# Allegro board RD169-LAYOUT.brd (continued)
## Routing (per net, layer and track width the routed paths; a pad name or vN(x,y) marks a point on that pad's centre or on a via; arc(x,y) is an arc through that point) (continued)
SIG232: length 12.4
  BOTTOM w0.5: F1.1 21.6,98.65 ; F1.1 19.4,98.65 ; F1.1 21.6,100.85 ; F1.1 19.4,100.85 ; F1.2 19.4,103.65 ; F1.2 19.4,105.85 ; F1.2 21.6,105.85 ; F1.2 21.6,103.65
SIG233: length 12.2
  BOTTOM w2: R34.1 R35.2
SIG236: length 5
  BOTTOM w0.8: R7.1 R6.2
SIG237: length 29.1
  BOTTOM w0.25: R6.1 47.6,125.58 ; R6.1 47.6,127.92 ; R6.1 48.48,126.75
  BOTTOM w0.4: C5.1 52,128.35 ; C5.1 50.65,127 ; C5.1 52,125.65
  BOTTOM w0.5: F1.4 21.6,119.15 ; F1.4 21.6,121.35 ; F1.4 19.4,121.35 ; F1.4 19.4,119.15 ; v4(53.5,127) 53.5,125.7 ; v4(53.5,127) 53.5,128.3 ; v4(53.5,127) 54.8,127 ; F1.3 19.4,116.35 ; F1.3 21.6,116.35 ; F1.3 21.6,114.15 ; F1.3 19.4,114.15 ; VAR1.1 17.26,130.11 ; VAR1.1 17.26,132.09 ; VAR1.1 19.24,132.09 ; VAR1.1 19.2,130.15
SIG239: length 5
  BOTTOM w0.4: C9.2 35.12,94.12 ; C9.2 36.88,94.12 ; C9.2 35.12,95.88 ; C9.2 36.88,95.88
SIG242: length 16.8
  BOTTOM w0.25: R7.2 36.15,127.92 ; R7.2 35.27,126.75 ; R7.2 36.15,125.58
  BOTTOM w0.4: C5.2 32,125.65 ; C5.2 33.35,127 ; C5.2 32,128.35
  BOTTOM w0.5: v4(30.5,127) 29.2,127 ; v4(30.5,127) 30.5,125.7 ; v4(30.5,127) 30.5,128.3 ; VAR1.2 26.74,126.89 ; VAR1.2 24.76,126.89 ; VAR1.2 26.74,124.91 ; VAR1.2 24.76,124.91
SIG245: length 8.1
  BOTTOM w0.3: R3.1 15.15,7 14.75,7.4 R2.2
SIG246: length 6.8
  BOTTOM w0.3: 44.35,3 40.65,3 40.4,2.75 R17.2 ; 44.35,3 R22.1 ; 44.35,3 C8.1
SIG247: length 2.8
  BOTTOM w0.3: R3.2 R4.1
SIG248: length 23.9
  TOP w0.3: v1(46.5,15.3) 47.5,14.3 47.5,8.9 45.27,6.67 v1(41,6.67)
  BOTTOM w0.3: D11.C 49.1,16.2 48.7,15.8 48.7,14.6 48.4,14.3 D12.C 46.7,14.3 46.5,14.5 v1(46.5,15.3) ; U1.7 v1(41,6.67)
SIG250: length 6.2
  BOTTOM w0.3: D7.A 47.2,9.4 46.6,10 R27.1
SIG255: length 2.7
  BOTTOM w0.4: R47.2 136.97,29.9 137.82,29.05 D17.C
SIG256: length 3.3
  BOTTOM w0.3: R9.2 51,10.5 49.55,11.95 D4.C
SIG267: length 137.3
  BOTTOM w0.4: U6.1 U6.2 142.26,35.63 139.75,33.12 139.75,29.35 140.22,28.88 141.75,28.88 146,24.62 146,5.5 142.62,2.12 106.88,2.12 100.1,8.9 95,8.9 92,5.9 92,3.12 90.25,1.38 54.92,1.38 D24.A
SIG270: length 1.3
  BOTTOM w0.4: U6.7 U6.6
SIG278: length 19.2
  TOP w0.8: v1(74.1,111.25) 72.5,111.25 69.36,114.39 v1(69.36,116.25)
  BOTTOM w0.8: U2.6 v1(69.36,116.25) 67.88,116.25 67.78,116.15 C10.1 ; v1(74.1,111.25) R26.2 74.1,108.38 73.72,108 C11.2
SIG280: length 3.9
  BOTTOM w0.8: 77.83,111.5 76.4,111.5 75.9,111 R26.1
SIG281: length 8
  BOTTOM w0.6: R14.1 68,123.85 67.95,123.9 C4.2
  BOTTOM w0.8: C4.2 65,122.88 65.1,122.78 R11.2
SIG283: length 2.9
  BOTTOM w0.8: R11.1 61.9,122.78 62,122.88 R10.2
SIG284: length 8.2
  BOTTOM w0.8: T1.3 74.38,122 74.05,122.33 72.25,122.33 72.25,120.47 71.91,120.12 U2.8
SIG285: length 2
  BOTTOM w0.8: R33.1 C18.2
SIG286: length 19.8
  TOP w0.8: T1.5 74.28,115.6 69,120.88 v1(69,122.4)
  BOTTOM w0.8: T1.5 79.15,115.6 81.17,113.58 81.17,111.5 ; R23.1 v1(69,122.4)
SIG287: length 7.7
  BOTTOM w0.8: 93.33,126.5 92,126.5 90.65,125.15 C18.1 88.05,125.15 88,125.2 T1.9
SIG288: length 10.2
  BOTTOM w0.8: R21.1 R18.1 63.4,118.75 64.03,119.38 68,119.38 ; R23.2 68,119.38 ; 68,119.38 68.09,119.28 U2.5
SIG290: length 5.7
  BOTTOM w0.8: U2.4 68.09,110.88 67.72,110.5 R8.1 R13.1
SIG316: length 2.1
  BOTTOM w0.8: 73.5,97.11 R67.1 73.5,99.25
SIG318: length 2.2
  BOTTOM w0.8: 73.5,92.75 R65.2 R66.1
SIG319: length 3
  BOTTOM w0.4: 78.5,45 R37.2 81.5,45
SIG320: length 3
  BOTTOM w0.4: 73.5,45 R36.2 R37.1 76.5,45
SIG321: length 2.2
  BOTTOM w0.8: 73.5,88.5 R64.2 R65.1 73.5,90.7
SIG322: length 7
  BOTTOM w0.3: 70,21 R40.1 R39.2 70,28
SIG323: length 2.2
  BOTTOM w0.8: 73.5,84.25 R63.2 R64.1 73.5,86.5
SIG328: length 54.4
  TOP w0.4: v1(72.25,30) v1(72.25,42)
  BOTTOM w0.3: 70,30 v1(72.25,30)
  BOTTOM w0.4: 81.5,43 80.5,42 v1(72.25,42) 67.62,42 65.5,44.12 65.5,51 66.75,52.25 C24.2
SIG332: length 2.3
  BOTTOM w0.5: R54.2 R55.1
SIG333: length 4
  BOTTOM w0.5: R53.2 R54.1
SIG334: length 2.3
  BOTTOM w0.5: R52.2 R53.1
SIG335: length 4
  BOTTOM w0.5: R55.2 R56.1
SIG341: length 15.8
  BOTTOM w0.4: R50.2 Q2.C Q5.C 60.5,98.85 62.85,101.2 R51.2
SIG345: length 15.4
  BOTTOM w0.4: U3.8 84.25,3.5 84.75,3 89.8,3 90.5,3.7 90.5,6.75 92,8.25 R42.2
SIG348: length 8.8
  BOTTOM w0.4: C29.1 70.6,99.65 69.2,101.05 D19.C 67.08,101.05 66.12,102 R51.1
SIG351: length 2.6
  BOTTOM w0.4: R20.1 77.16,9.75 77.25,9.65 U3.4
SIG353: length 7.2
  BOTTOM w0.4: Q2.B 63.55,95 64.05,94.5 65.88,94.5 66.38,94 66.38,92.25 66.88,91.75 R30.1
SIG354: length 4.9
  BOTTOM w0.3: C7.1 80.65,6.57 80.1,7.12 U3.2
SIG356: length 5.7
  BOTTOM w0.3: U3.5 83.1,9.65 82.65,10.11 R29.1 C16.1
SIG357: length 4.9
  BOTTOM w0.3: R31.1 57.5,2.55 57.75,2.3 Q3.B
SIG358: length 2.6
  BOTTOM w0.3: C14.1 79.4,12.5 80.15,11.75 R29.2
SIG359: length 19.6
  BOTTOM w0.3: U3.3 80,8.38 80.12,8.51 80.12,10.75 79.88,11 77.5,11 77,11.5 R19.2
  BOTTOM w0.4: 76.15,6.75 73,6.75 72.7,6.45 D5.C ; 76.15,6.75 C6.1 77,7.75 77.64,8.38 U3.3 ; 76.15,6.75 R15.1
SIG381: length 14
  BOTTOM w0.4: R78.2 90.38,75.4 90.45,75.33 92.88,75.33 92.95,75.25 R82.1 94.35,74.61 Q8.G
SIG383: length 13.6
  TOP w0.4: Q7.G 79.96,71.5 80,71.54 v1(80,77.12)
  BOTTOM w0.4: R81.1 v1(80,77.12) 80,78.33 78.58,78.33 78.5,78.4 R77.2
SIG387: length 5.6
  BOTTOM w0.4: R74.1 R77.1 78.5,81.6 78.58,81.67 80,81.67
SIG392: length 4.8
  BOTTOM w0.4: R76.1 R78.1 90.38,78.6 90.45,78.67 91.75,78.67
SIG395: length 9.3
  BOTTOM w0.4: C46.2 97.38,92.5 98.4,93.53 R86.1 98.4,95.4 99.4,96.4 R73.2 R85.1
SIG396: length 15.7
  TOP w0.4: v1(94.75,96.12) 95.25,95.62 95.25,92.25 v2(98,89.5)
  BOTTOM w0.4: C51.1 93.85,97.03 v1(94.75,96.12) ; C51.1 93,98.25 92.9,98.35 R117.2 ; C51.1 C52.1 ; v2(98,89.5) C44.2
SIG401: length 10
  BOTTOM w0.4: 90,102.35 R59.1 R72.2 R71.2 ; 90,102.35 88.94,102.35 88.69,102.1 U5.8 ; 90,102.35 C28.1
SIG404: length 1.9
  BOTTOM w0.4: R70.2 C30.1
SIG406: length 6.2
  BOTTOM w0.4: U5.7 87.42,99.75 87.67,99.5 89.5,99.5 90.15,100.15 R117.1
SIG407: length 18.2
  TOP w0.4: v1(80,85.75) 80,91.66 v1(82.34,94)
  BOTTOM w0.4: C38.2 82,96.9 82.34,96.56 U5.14 v1(82.34,94) ; 80,84.08 D22.C v1(80,85.75)
SIG409: length 2.2
  BOTTOM w0.4: 94.17,86.5 R97.2
SIG415: length 2.5
  BOTTOM w0.4: R88.2 156.5,109.15 156.65,109 C50.2
SIG416: length 2.4
  BOTTOM w0.4: C55.1 178.05,121.85 177.95,121.75 U9.3
SIG417: length 4.7
  BOTTOM w0.4: R89.1 158.6,101.85 159.1,101.35 C49.1
SIG418: length 2.4
  BOTTOM w0.4: U8.3 177.95,105.25 178.05,105.35 C53.1
SIG420: length 8
  BOTTOM w0.4: R98.2 182,101.6 181.5,102.1 C54.1 179.7,102.1 179,101.4 U8.4
SIG422: length 2.6
  BOTTOM w0.4: R94.1 Q13.4
SIG423: length 2.6
  BOTTOM w0.4: R95.1 Q11.4
SIG425: length 27.4
  TOP w0.4: v1(158.5,113.6) v1(171.5,113.6) v1(171.5,118.35)
  BOTTOM w0.4: R92.2 v1(171.5,113.6) ; v1(158.5,113.6) R93.2 ; U9.1 176.05,119.9 174.5,118.35 R96.2 v1(171.5,118.35)
SIG426: length 2.6
  BOTTOM w0.4: R92.1 Q12.4
SIG430: length 2.8
  BOTTOM w0.4: R93.1 Q10.4
SIG431: length 27.8
  TOP w0.4: v1(158.62,97.1) v1(171.5,97.1) v1(171.5,102.35)
  BOTTOM w0.4: v1(158.62,97.1) R95.2 ; v1(171.5,102.35) R91.2 175.15,102.35 176.05,103.25 U8.1 ; R94.2 v1(171.5,97.1)
SIG435: length 6.8
  BOTTOM w0.4: U9.4 179.03,117.9 179.47,118.35 C58.1 181.28,118.35 182,117.62 R99.1
SIG438: length 2.7
  BOTTOM w0.4: R110.1 158.6,35.5 158.5,35.4 R109.2
SIG439: length 3
  BOTTOM w0.4: R110.2 162.85,34 162.9,33.95 R111.1
SIG440: length 2.3
  BOTTOM w0.4: R116.1 168.09,13.24 Q16.4
SIG441: length 33.6
  BOTTOM w0.3: C80.1 169.1,25.1 ; C80.1 168.25,24.25 ; C80.1 169.1,23.4 ; C80.1 169.95,24.25 ; C78.2 168.75,29.4 C81.1
  BOTTOM w0.4: C65.1 157.78,15.4 157.83,15.35 U11.1 160.97,15.35 162.25,16.62 162.25,17.89 ; U11.6 163.15,17.89
  BOTTOM w1: TB2.4 181.37,29.63 ; TB2.4 181.37,26.37 ; TB2.4 184.63,26.37 ; TB2.4 184.63,29.63 ; TB2.3 184.63,37.37 ; TB2.3 181.37,40.63 ; TB2.3 181.37,37.37 ; TB2.3 184.63,40.63
SIG442: length 2.8
  BOTTOM w0.3: C73.2 164.4,13.2 164.5,13.3 U11.8
SIG444: length 2.3
  BOTTOM w0.4: Q15.4 174.59,13.24 R115.1
SIG445: length 2.3
  BOTTOM w0.4: R113.1 181.09,13.24 Q14.4
SIG446: length 2.8
  BOTTOM w0.4: R104.1 157.28,17.35 158.01,16.61 U11.2
SIG447: length 3
  BOTTOM w0.4: R112.1 166.15,34 166.1,33.95 R111.2
SIG452: length 11
  BOTTOM w0.3: R101.1 146.78,56.6 148.03,55.35 148.75,55.35 ; R100.2 149.25,55.35 ; 149.25,55.35 148.75,55.35 ; 149.25,55.35 149,55.1 ; 149,55.1 148.75,55.35 ; 149,55.1 ZD3.C 149,53.58
SIG454: length 3.1
  BOTTOM w0.3: R105.1 141.15,58.85 141.5,59.2 141.5,59.9 141.85,60.25 C64.1
SIG455: length 7.8
  BOTTOM w0.3: C68.1 R107.1 146.15,62.35 147.62,60.88 147.62,59.67 148.05,59.25 R106.2
SIG458: length 13.5
  BOTTOM w0.3: 148.95,65.5 D25.A 148.95,68.42 148.4,68.97 C70.2 ; 148.95,65.5 151.5,65.5 151.75,65.25 R114.1 ; 148.95,65.5 147.88,65.5 147.55,65.17 D26.C
SIG460: length 11.6
  TOP w0.3: v2(145.4,61.12) v2(145.4,67.75)
  BOTTOM w0.3: 145.4,60.4 145.25,60.25 C64.2 ; 145.4,60.4 v2(145.4,61.12) ; 145.4,60.4 R103.2 ; U10.1 145,66.35 145.4,66.75 v2(145.4,67.75)
SIG461: length 11.3
  BOTTOM w0.3: R25.1 R24.2 46.62,6 46,6.62 46,8.55 45.75,8.8 44.12,8.8 43.3,7.97 U1.5
SIG462: length 4.1
  BOTTOM w0.3: U1.1 38.8,5.2 38.6,5 R16.2 R17.1
SIG464: length 7.2
  BOTTOM w0.4: U5.9 88.69,94.43 89.03,94.1 C34.1 ; C34.1 R80.1 ; C34.1 R79.2
SIG466: length 18.6
  TOP w0.4: v1(90.25,98.62) 96.12,98.62 v1(96.75,99.25)
  BOTTOM w0.4: R73.1 97.6,98.9 97.25,99.25 v1(96.75,99.25) ; v1(90.25,98.62) 87.25,98.62 86.16,99.72 U5.6 86.16,102.5 86.41,102.75 87.75,102.75 88,103 C27.1
SIG469: length 4
  BOTTOM w0.3: R62.1 R60.2 R61.1
SIG470: length 9.8
  BOTTOM w0.3: 24.75,2.62 24.75,3.85 23.85,4.75 R48.2 23.85,6.25 24.75,7.15 24.75,9.88 24.45,10.18 U4.2
SIG471: length 4.8
  BOTTOM w0.3: R69.1 20.4,10.5 ; 20.4,10.5 R62.2 ; 20.4,10.5 21.75,10.5 22.07,10.82 U4.3
SIG489: length 6.2
  BOTTOM w0.3: U1.6 43.5,7.33 43.75,7.08 43.75,6.3 44,6.05 D7.C 45.65,6.05 46.15,5.55 R22.2
SIG490: length 3.4
  BOTTOM w0.3: D3.C 69.8,7.47 69.05,6.72 D5.A
SIG491: length 13.8
  BOTTOM w0.3: U10.2 142.55,65.15 142.75,64.95 C68.2 ; R105.2 R108.1 141.48,62.85 141.75,63.12 141.75,63.77 142.12,64.15 C68.2 ; D25.C 146.55,64.7 146,64.15 R107.2 C68.2
SIG508: length 72.6
  TOP w0.4: v1(121.75,64.02) 121.75,65 114.75,72 114.75,82.88 113.12,84.5 97.88,84.5 93.53,88.85 v1(93.5,88.85) 93.5,90.88 88.5,95.88 86,95.88 84.89,96.99 v1(84.89,98.88)
  BOTTOM w0.4: PC1.C v1(121.75,64.02) ; v1(93.5,88.85) R70.1 94.75,88 95,87.75 97.78,87.75 98.15,87.38 R97.1 ; U5.5 v1(84.89,98.88)
SIG519: length 7.5
  BOTTOM w0.3: R32.1 20,22.18 19.75,22.43 17,22.43 17,25.99 17.02,26.02
SIG520: length 2.4
  BOTTOM w0.3: 13.25,22.68 R12.2
SIG521: length 2.3
  BOTTOM w0.8: 72.25,125.67 70.9,125.67 70.88,125.65 R14.2
SIG522: length 2.2
  BOTTOM w0.4: 80,87.42 R83.1
SIG529: length 44.5
  BOTTOM w0.4: 86.25,15.93 86.33,15.85 R46.2 91.9,15.85 96.63,11.12 100.88,11.12 107.62,4.38 117.88,4.38 118.9,5.4 R49.2 118.9,9.72 118.2,10.43 Q6.1
SIG535: length 23.3
  TOP w2: R34.2 29.85,22.65 RL1.4
  BOTTOM w0.5: D10.4 51.13,49.62 ; D10.4 48.87,49.62 ; D10.4 48.87,51.88 ; D10.4 51.13,51.88
SIG536: length 23.6
  TOP w0.4: C23.1 24.8,39.45 ; C23.1 26.7,37.55 ; C23.1 26.7,39.45 ; C23.1 24.8,37.55
  TOP w0.5: D10.1 26.13,49.62 ; D10.1 23.87,49.62 ; D10.1 23.87,51.88 ; D10.1 26.13,51.88
  BOTTOM w0.4: C23.1 26.7,39.45 ; C23.1 24.8,37.55 ; C23.1 24.8,39.45 ; C23.1 26.7,37.55
  BOTTOM w0.5: D10.1 26.13,51.88 ; D10.1 23.87,51.88 ; D10.1 23.87,49.62 ; D10.1 26.13,49.62
U8_5: length 5.7
  BOTTOM w0.3: C49.2 160.05,99.25 ; C49.2 160.9,98.4 ; C49.2 161.75,99.25 ; C49.2 160.9,100.1
  BOTTOM w0.4: 176.09,99.1 176.05,99.14 U8.5
  vias: v3(138.5,99) v3(138.5,97) v3(138.5,95) v3(138.5,93) v3(138.5,91) v3(140.5,100) v3(140.5,98) v3(140.5,96) v3(140.5,94) v3(140.5,92) v3(140.5,90) v3(142.72,90) v3(142.75,96) v3(145.01,100) v3(145,98) v3(145,96) v3(145,94) v3(145,92) v3(145,90)
U9_5: length 4.1
  BOTTOM w0.3: R88.1 156.5,114.55 ; R88.1 156.5,112.65 ; R88.1 155.25,113.6 ; U9.5 176.05,116.95
  vias: v3(138.5,131.5) v3(138.5,129.5) v3(138.5,127.5) v3(138.5,125.5) v3(138.5,123.5) v3(138.5,121.5) v3(140.5,132.5) v3(140.5,130.5) v3(140.5,128.5) v3(140.5,126.5) v3(140.5,124.5) v3(140.5,122.5) v3(140.5,120.5) v3(142.75,132.5) v3(142.75,130.5) v3(142.75,124.5) v3(145,132.5) v3(145,130.5) v3(145,128.5) v3(145,126.5) v3(145,124.5) v3(145,122.5) v3(145,120.5) v3(147,131.53) v3(147,129.53) v3(147,127.53) v3(147,125.38) v3(147,123.38)
VREF: length 15.5
  BOTTOM w0.3: R84.2 C43.1 31.95,11.4 32.75,10.6 U7.2 U7.1 35.9,10.6 36.15,10.35 C3.1 39.62,8.75 39.88,8.5 39.88,6.92 39.62,6.67 U1.2
VSENSE: length 52.2
  BOTTOM w0.3: 70,19 R40.2 70,17 63,10 Q4.C ; Q4.C 63,3.5 62.75,3.25 Q3.C ; Q4.C 69.12,4.25 70.47,2.9 82,2.9 82.6,3.5 82.6,8.13 82.85,8.38 U3.6 85.64,8.38 85.75,8.5 R41.1
  BOTTOM w0.4: C21.1 R41.1

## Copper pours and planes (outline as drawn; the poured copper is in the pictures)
12VREC on TOP: outline of 183 points within 137.5,9.5 191,134 ; 30 cut-outs
12VREC on BOTTOM: outline of 139 points within 161,9 191,16.88 ; 2 cut-outs
12VREC on BOTTOM: 138,102 137.5,102.5 137.5,118.2 138.05,118.75 145.45,118.75 146,118.2 146,102.5 145.5,102
GND_PRI_P on TOP: 62,114.94 62.01,115 62.04,115.04 62.46,115.46 62.5,115.49 62.56,115.5 62.97,115.5 63.12,115.38 63.03,115.21 62.58,114.92 62.29,114.47 62.12,114.38 62,114.53
GND_PRI_P on TOP: 135.72,71 118,71 116,73 116,86.5 116.5,87 119.5,87 120,86.5 120,76.5 121,75.5 134.49,75.5 137,78.01 137,82.18 137.82,83 140,83 140.5,82.5 140.5,75.78 ; 3 cut-outs
GND_PRI_P on TOP: outline of 192 points within 62,101.75 107,130.5 ; 5 cut-outs
GND_PRI_P on TOP: outline of 615 points within 62,82 101.5,113 ; 2 cut-outs
GND_PRI_P on TOP: outline of 153 points within 65,8.1 121,87
GND_PRI_P on BOTTOM: 135,50.38 99.12,50.38 98.5,51 98.5,60.5 99,61 102.36,61 105,63.64 105,66.8 104.3,67.5 104.3,70 108,73.7 108,85.17 110.21,87.38 110.28,87.45 114.5,91.67 114.5,119.12 114,119.62 103.38,119.62 101,117.25 101,111.8 100.45,111.25 98.75,111.25 98.75,111.94 99.97,113.16 100,113.18 100.04,113.22 100.06,113.25 100.08,113.27 100.09,113.3 100.11,113.32 100.14,113.38 100.16,113.43 100.18,113.49 100.19,113.55 100.2,113.61 100.2,113.67 100.2,113.71 100.2,124.1 100.35,124.25 118.05,124.25 120,122.3 120,79 120.37,78.63 120.83,78.17 121,78 136.8,78 136.97,78.17 137.3,78.5 137.3,82.5 137.8,83 139.8,83 140.3,82.5 140.3,75.79 136.01,71.5 135.14,71.5 134.14,70.5 131.76,70.5 127.76,66.5 120.38,66.5 119.38,65.5 119.38,60.13 119.74,59.75 120.38,59.12 127.76,59.12 131.89,55 135,55 135.5,54.5 135.5,50.87 ; 6 cut-outs
GND_PRI_P on BOTTOM: outline of 738 points within 60.95,82.5 101,110.75 ; 19 cut-outs
GND_PRI_P on BOTTOM: outline of 98 points within 77.35,100.2 81.75,103.99
GND_PRI_P on BOTTOM: 115.7,7.5 108.5,7.5 101.62,14.38 97.62,14.38 93.12,18.88 87.21,18.88 83.58,22.5 78.5,22.5 78,23 78,26 78.5,26.5 91.91,26.5 93,27.59 93,33 93.5,33.5 112.5,33.5 113,33 113,30.25 112.5,29.75 105.88,29.75 104.5,28.37 104.5,14.88 105.88,13.5 115.95,13.5 116.2,13.25 116.2,8 ; 3 cut-outs
GND_PRI_P on BOTTOM: outline of 150 points within 60.5,103 92.25,119.7 ; 8 cut-outs
GND_PRI_P on BOTTOM: 95.4,113.3 95.4,111.38 95.22,111.51 94.27,112.47 94.25,112.5 94.2,112.54 94.18,112.56 94.15,112.58 94.13,112.59 94.1,112.61 94.05,112.64 93.99,112.66 93.93,112.68 93.87,112.69 93.81,112.7 93.75,112.7 93.72,112.7 93.35,112.7 93.31,112.74 93.24,112.81 93.17,112.87 93.09,112.93 93.01,112.98 92.92,113.02 92.83,113.05 92.74,113.08 92.64,113.09 92.55,113.1 92.45,113.1 92.36,113.09 92.26,113.08 92.17,113.05 92.08,113.02 91.99,112.98 91.91,112.93 91.83,112.87 91.76,112.81 91.69,112.74 91.63,112.67 91.57,112.59 91.52,112.5 89.08,112.5 90.46,113.88 92.17,113.88 92.49,114.04 93.09,114.63 93.24,114.91 93.25,115.02 93.25,119.7 95.8,119.7 98.8,122.7 98.8,113.96 97.96,113.12 97.1,113.12 97.1,113.3 ; 1 cut-out
GND_PRI_P on BOTTOM: 69,53.5 68.5,54 68.5,67.62 65,71.12 65,77.48 65.5,77.97 68.5,77.97 69,77.48 69,71.88 72.5,68.38 72.5,54 72,53.5
GND_PRI_S on TOP: outline of 1022 points within 14.5,1 155,44.5 ; 4 cut-outs
GND_PRI_S on BOTTOM: outline of 132 points within 57.95,2 69.86,9.75
GND_PRI_S on BOTTOM: outline of 130 points within 83.1,3.5 90.33,14.62 ; 4 cut-outs
GND_PRI_S on BOTTOM: outline of 255 points within 36.6,1 57.26,6.59
GND_PRI_S on BOTTOM: outline of 107 points within 134.25,26.75 144.4,38.25
GND_PRI_S on BOTTOM: outline of 542 points within 15.88,1.7 43.84,20.25 ; 7 cut-outs
GND_PRI_S on BOTTOM: outline of 367 points within 63.45,3.35 117.4,22 ; 6 cut-outs
GND_PRI_S on BOTTOM: 142.12,29.21 141.88,29.36 141.82,29.39 141.8,29.46 141.8,30.6 141.55,30.6 141.48,30.63 141.45,30.7 141.45,32.95 141.46,32.99 141.48,33.02 142.29,33.84 142.33,33.86 142.36,33.87 142.4,33.87 142.47,33.84 142.5,33.77 142.5,32.49 144.2,32.49 144.2,33.77 144.23,33.84 144.3,33.87 144.43,33.87 144.51,33.85 144.55,33.77 144.55,33.7 145.95,33.7 145.95,33.8 145.98,33.87 146.05,33.9 146.45,33.9 146.52,33.87 146.55,33.8 146.55,33.7 147.95,33.7 147.95,35.1 146.55,35.1 146.55,35 146.52,34.93 146.45,34.9 146.05,34.9 145.98,34.93 145.95,35 145.95,35.1 145.9,35.1 145.83,35.13 145.8,35.2 145.8,35.9 145.83,35.97 145.9,36 147.83,36 147.87,35.99 147.9,35.97 148.35,35.53 148.37,35.5 148.38,35.46 148.38,31.92 148.37,31.88 148.35,31.85 146.1,29.6 146.1,25.7 146.07,25.63 146,25.6 145.77,25.6 145.74,25.61 145.7,25.63 ; 2 cut-outs
GND_SEC on TOP: 136.5,64.44 136.51,64.5 136.54,64.54 137.46,65.46 137.5,65.49 137.56,65.5 138.63,65.5 143.83,70.71 143.88,70.74 143.94,70.75 146.94,70.75 147,70.74 147.04,70.71 147.46,70.29 147.49,70.25 147.5,70.19 147.5,63.58 147.77,63.31 151.18,59.9 151.46,59.63 151.49,59.58 151.5,59.52 151.5,56.69 151.49,56.63 151.46,56.58 151.04,56.17 151,56.14 150.94,56.12 145.95,56.12 145.89,56.14 145.83,56.19 145.08,57.21 144.19,58.23 143.21,59.16 142.47,59.75 142.15,60.01 141.03,60.76 140.25,61.18 139.84,61.41 138.6,61.95 137.32,62.39 136.74,62.54 136.7,62.56 136.67,62.58 136.54,62.71 136.51,62.75 136.5,62.81 ; 1 cut-out
GND_SEC on BOTTOM: outline of 808 points within 140.95,1 191,126 ; 49 cut-outs
GND_SEC on BOTTOM: outline of 159 points within 137.38,62.34 148.5,70.75 ; 1 cut-out
+HV on TOP: 127,17 126,18 126,27 127,28 145,28 146,27 146,18 145,17
+HV on BOTTOM: 141.5,17.25 126.5,17.25 126,17.75 126,38.83 124.33,40.5 87.5,40.5 86,42 86,50.8 85.57,51.23 82.2,54.6 80.1,54.6 78.23,56.47 77.5,57.2 77.5,62.25 81.65,66.4 81.65,69.45 81.9,69.7 83.1,69.7 83.35,69.45 83.35,66.4 84.15,65.6 84.15,61.65 84.8,61 95.5,61 96.5,60 96.5,50.17 98.3,48.38 136,48.38 136.5,47.88 136.5,41.75 133.93,39.18 132,37.25 132,26.88 134.38,24.5 141.5,24.5 142,24 142,17.75 ; 3 cut-outs
FG1 on BOTTOM: 190,1 177.5,1 177,1.5 177,7.5 177.5,8 190.5,8 191,7.5 191,2 ; 1 cut-out
FG2 on BOTTOM: 3.6,77.5 1,80.1 1,133 2,134 8,134 9,133 9,126.75 8,125.75 5.25,125.75 4,124.5 4,83 5.25,81.75 13,81.75 14,80.75 14,78.5 13,77.5
FG3 on BOTTOM: 8,1 1.5,1 1,1.5 1,45.5 1.5,46 5.25,46 6,45.25 6,30.5 4.25,28.75 4.25,10.25 8.5,6 8.5,1.5 ; 2 cut-outs
HS on BOTTOM: 101.66,63.12 97.59,63.12 93.42,67.3 84.45,67.3 84.19,67.56 84.19,69.45 84.44,69.7 94.55,69.7 98.63,65.62 100.62,65.62 101.65,66.65 101.65,73.71 101.79,73.85 102.5,74.56 102.5,87 103.38,87.88 105.3,89.8 108.25,92.75 108.25,104.5 108.24,104.81 108.2,105.11 108.13,105.41 108.04,105.7 107.92,105.98 107.8,106.21 107.78,106.25 107.62,106.51 107.43,106.75 107.23,106.98 107,107.18 106.76,107.37 106.5,107.53 106.23,107.67 105.95,107.79 105.66,107.88 105.35,107.95 105.06,107.99 104.75,108 103.5,108 103,108.5 103,112 103.5,112.5 112,112.5 112.5,112 112.5,92.5 108.96,88.96 107.74,87.74 106,86 106,74.53 105.44,73.97 103.35,71.88 103.35,64.81 ; 1 cut-out
ISENSE on BOTTOM: 30.7,14.3 29.2,14.3 28.6,14.9 28.6,18.3 29.8,19.5 32.8,19.5 36.1,22.8 36.1,28.85 47.25,40 80.25,40 80.75,39.5 80.75,34.67 82.42,33 91.5,33 92,32.5 92,28 91.5,27.5 78.5,27.5 78,28 78,30.75 77.5,31.25 73.75,31.25 69.9,35.1 48.5,35.1 44.57,31.17 43.67,30.27 42.5,29.1 42.5,23.2 40,20.7 36.82,17.52 36.67,17.37 36.5,17.2 33.6,17.2 ; 4 cut-outs
ISNS_VCR on TOP: 134.75,83.5 124.25,83.5 123.75,84 123.75,89.45 117.1,96.1 103.4,96.1 102.8,96.7 102.8,100.6 103.4,101.2 121.5,101.2 123,99.7 123,98.5 124.5,97 124.8,97 135.25,86.55 135.25,84 ; 3 cut-outs
SIG219 on BOTTOM: 44.8,86.6 41.7,86.6 41.1,87.2 41.1,89.1 41.6,89.6 42.3,89.6 46.5,93.8 46.5,103.5 47.2,104.2 51.5,104.2 52.5,103.2 52.5,94.3 ; 1 cut-out
SIG222 on BOTTOM: 38.54,73.84 39.96,75.26 40,75.29 40.06,75.3 55.14,75.3 55.24,75.26 56.56,73.94 56.59,73.9 56.6,73.84 56.6,69.76 56.56,69.66 55.32,68.42 54.84,67.94 54.8,67.91 54.74,67.9 46,67.9 44.5,66.4 44.5,48.81 44.46,48.71 44.04,48.29 44,48.26 43.94,48.25 41.06,48.25 40.96,48.29 40.54,48.71 40.51,48.75 40.5,48.81 40.5,69.1 38.54,71.06 38.51,71.1 38.5,71.16 38.5,73.74 ; 2 cut-outs
SIG226 on BOTTOM: 12.5,55.44 12.51,55.5 22.6,65.6 22.6,77.34 22.61,77.4 27.96,82.76 27.99,82.78 28.03,82.8 28.06,82.8 51.6,82.8 52.8,84 52.8,88.44 52.81,88.5 53.46,89.16 53.49,89.18 53.53,89.2 53.56,89.2 56.04,89.2 56.1,89.19 56.89,88.4 56.9,88.34 56.9,79.96 56.89,79.9 55.34,78.34 55.31,78.32 55.27,78.3 55.24,78.3 31.7,78.3 30.37,76.97 29.25,75.85 28.6,75.2 28.6,65.5 30.9,63.2 34.46,63.2 34.55,63.17 34.6,63.1 36.99,60.7 37,60.64 37,48.81 36.99,48.75 36.54,48.29 36.51,48.27 36.47,48.25 36.44,48.25 33.31,48.25 33.25,48.26 33.21,48.29 32.79,48.71 32.76,48.75 32.75,48.81 32.75,55.75 30.4,58.1 18.4,58.1 16,55.7 16,41.31 15.99,41.25 15.54,40.79 15.51,40.77 15.47,40.75 15.44,40.75 13.06,40.75 13,40.76 12.96,40.79 12.54,41.21 12.51,41.25 12.5,41.31 ; 3 cut-outs
SIG231 on TOP: 121.5,8 121,8.5 121,13.12 119.12,15 106.5,15 106,15.5 106,27.75 106.5,28.25 123.6,28.25 124.5,27.35 124.5,17.38 126.07,15.81 126.19,15.69 126.38,15.5 145,15.5 146,14.5 146,8.5 145.5,8
SIG231 on BOTTOM: 122,5 121,6 121,13.12 119.12,15 106.5,15 106,15.5 106,27.75 106.5,28.25 113.12,28.25 114.5,29.63 114.5,33.62 113.12,35 83.25,35 83.21,35.04 82.75,35.5 82.75,39 83.25,39.5 85.67,39.5 86.67,38.5 123.5,38.5 124,38 124,16.94 125.69,15.25 134.1,15.25 134.1,13.45 137.9,13.45 137.9,15.25 142,15.25 142.5,14.75 142.5,6 141.5,5
SIG237 on BOTTOM: 22.5,113.5 17.8,113.5 16,115.3 16,133 17,134 53.5,134 55.12,132.38 55.12,124.62 53,122.5 53,116.25 52.82,116.07 51.75,115 48.87,115 47.81,116.07 47,116.87 47,125.7 48.35,125.7 48.35,127.8 47,127.8 47,130.3 46.17,131.12 24,131.12 21.5,128.62 21.5,123 24.5,120 24.5,115.5 ; 4 cut-outs
SIG239 on BOTTOM: 30.2,86.7 24.1,86.7 23.5,87.3 23.5,89.5 24,90 26.12,90 31.5,95.38 31.5,103.2 32.8,104.5 37,104.5 38.1,103.4 38.1,94.6 ; 1 cut-out
SIG242 on BOTTOM: 17.96,87.5 10.75,87.5 9.5,88.75 9.5,91.3 10.99,92.79 11.76,93.56 16.43,93.56 18.37,95.5 23.04,95.5 25.25,97.71 25.25,112.25 26.25,113.25 26.44,113.44 27,114 27,121.02 24,124.02 24,127.5 25.12,128.62 36.25,128.62 36.75,128.13 36.75,127.8 35.4,127.8 35.4,125.7 36.75,125.7 36.75,114.05 33.34,110.64 30.69,107.99 29.96,107.26 28.75,106.05 28.75,96.25 26.58,94.08 25.14,92.65 25,92.5 22.96,92.5 ; 2 cut-outs
SIG441 on BOTTOM: outline of 83 points within 162,17 191,44.5 ; 3 cut-outs
SIG535 on BOTTOM: 30.8,23.6 29.2,23.6 28.3,24.5 28.3,28.4 31.03,31.13 31.27,31.37 34.2,34.3 34.71,34.81 37.14,37.24 38.4,38.5 40.08,40.18 42.08,42.18 43.02,43.12 45.76,45.86 48,48.1 48,52.75 48.5,53.25 51.5,53.25 52,52.75 52,48.5 49.22,45.72 49.03,45.53 40.22,36.72 38.17,34.67 37.28,33.78 34.49,30.99 34.35,30.85 31.8,28.3 31.8,24.6 ; 1 cut-out
SIG536 on TOP: 58.13,9 56.5,9 55,10.5 55,13.24 53.8,14.44 50.25,18 48.5,19.76 48.5,30.5 47.5,31.5 39.5,31.5 36.64,34.36 35.5,35.5 24,35.5 23.41,36.09 23,36.5 23,51.5 24,52.5 29.5,52.5 30,52 30,50.5 30.02,50.06 30.08,49.63 30.17,49.21 30.3,48.79 30.47,48.39 30.67,48 30.9,47.63 31.17,47.29 31.38,47.06 31.46,46.96 31.79,46.67 32.13,46.4 32.5,46.17 32.89,45.97 33.29,45.8 33.71,45.67 34.13,45.58 34.56,45.52 35,45.5 50,45.5 50.37,45.51 50.81,45.57 51.23,45.66 51.65,45.78 52.06,45.94 52.45,46.14 52.82,46.37 53.17,46.63 53.49,46.92 53.62,47.06 53.79,47.24 54.06,47.58 54.3,47.95 54.5,48.33 54.68,48.73 54.81,49.15 54.91,49.57 54.97,50 55.47,50.5 59,50.5 59.5,50 59.5,10.37 ; 3 cut-outs
SIG536 on BOTTOM: 27,35.9 23.6,35.9 23,36.5 23,52.75 23.5,53.25 27,53.25 27.5,52.75 27.5,36.4 ; 2 cut-outs
U8_5 on TOP: 140.5,88 137.5,91 137.5,100.5 138,101 146,101 147,100 147,89 146,88
U8_5 on BOTTOM: 146,88 140.5,88 137.5,91 137.5,100.5 138,101 145.91,101 147.41,102.5 155.65,102.5 155.65,101.05 157.85,101.05 157.85,101.35 158.39,101.35 158.6,101.14 158.6,99.95 158.4,99.95 158.4,98.55 159.8,98.55 159.8,99.95 159.6,99.95 159.6,101.33 159.44,101.72 158.97,102.19 158.81,102.3 158.23,102.5 168.6,102.5 170.85,100.25 180.63,100.25 181.2,99.68 181.2,96.07 180.63,95.5 147.29,95.5 146.5,94.71 146.5,88.5 ; 4 cut-outs
U9_5 on TOP: 138,119.5 137.5,120 137.5,133 138.5,134 147.2,134 148.2,133 148.2,122.7 145,119.5
U9_5 on BOTTOM: outline of 125 points within 137.5,112 181.12,134 ; 4 cut-outs

Small or netless copper shapes (teardrops, artwork), in the pictures only: 96 on TOP, 96 on BOTTOM

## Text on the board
BOTTOM: L2 PATTERN HANDA | PC132-01-00
Board Geometry/Soldermask Bottom: L2 RESIST HANDA | PC132-01-00
TOP: PC132-01-00 | L1 PATTERN BUHIN
Board Geometry/Soldermask Top: PC132-01-00 | L1 RESIST BUHIN
Ref Des/Silkscreen Top: 1 | 4 | 3 | 2 | 5 | 10 | 6 | 7 | 14 | 8
SYMBOL-1-TOP: PC132-01-00 | L1 SILK BUHIN
SYMBOL-2-TOP: PC132-01-00 | L1 SILK BUHIN
User.5: L2 SILK HANDA | PC132-01-00
User.6: L2 SILK HANDA | PC132-01-00
